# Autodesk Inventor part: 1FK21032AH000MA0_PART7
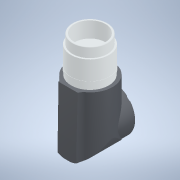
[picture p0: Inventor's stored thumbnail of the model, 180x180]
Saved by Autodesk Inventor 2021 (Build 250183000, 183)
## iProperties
Created: 2025-04
Part Number: 1FK21032AH000MA0_PART7
Material: Generic
Catalog Web Link: www.3dfindit.com
Description: -Servo synchronous motor
Document SubType Name: Modeling
Designer: psAdmin
Mass: 11.1504 g
Surface Area: 35.8996 cm^2
Volume: 11.1504 cm^3
Density: 1 g/cm^3
Appearance: PSOLRGB-176-176-176
Category: PARTsolutions
Title: 1FK21032AH000MA0_PART7
Author: Cadenas PARTsolutions
Comments: Servo synchronous motor
Sending System: PARTsolutions
Preprocessor: ST-DEVELOPER v19.3
PSOL_IDENT_0: {$CADENAS_DATA/23d-libs/siemens_ag/_cat_/45/10/1fk21032ah000ma0.prj},213 {VTYP=3D},{NB=1FK21032AH000
PSOL_IDENT_1: MA0_PART7},{LINA=1FK21032AH000MA0_PART7},{NN=1FK21032AH000MA0_PART7},{NOPRJ=TRUE},{DATE=19.08.2025 1
PSOL_IDENT_2: 4:00:35},{GEOMDATE=30.07.2025 02:02:03},{VERSION=},{LINEID=10},{WBVAR=},{WBNUMERIC=}  {NB=1FK21032AH
PSOL_IDENT_3: 000MA0_PART7},{LINA=1FK21032AH000MA0_PART7},{KT=DUMMY},{PREVIEW=../../../_pool_/14/8e/p_d211_xx_0042
PSOL_IDENT_4: 6j.png},{DESCSHORT=SIMOTICS S-1FK2 HD, SINAMICS S210 3AC 400V-480V, 0.59 Nm, 4500 rpm},{DESCLONG=SIM
PSOL_IDENT_5: OTICS S-1FK2 HD servo motor M0=0.64 Nm; PN = 0.28 kW at nN=4500 rpm (380-480 V); PN = 0.167 kW at nN=
PSOL_IDENT_6: 2500 rpm (200-240 V); degree of protection IP64; cylindrical shaft D14 x 30 mm; absolute encoder 22-
PSOL_IDENT_7: bit + 12-bit multiturn (encoder AM22DQC); with OCC interface; plug size M17, rotatable; SIMOTICS S-1
PSOL_IDENT_8: FK2 servomotorfor a wide range of uses in industrial environments. SIMOTICS S‑1FK2 servomotors are c
PSOL_IDENT_9: ompact synchronous motors with a high dynamic performance that set themselves apart as a result of t
PSOL_IDENT_10: heir high power density, degree of protection and overload capability. The motors are available in t
PSOL_IDENT_11: wo variants: as High Dynamic variant (highest dynamic performance as a result of the low intrinsic m
PSOL_IDENT_12: oment of inertia for applications demanding a high dynamic performance with low moved masses) - and
PSOL_IDENT_13: as Compact variant (precise and stable closed-loop control for medium up to large moved masses as a
PSOL_IDENT_14: result of a medium intrinsic moment of inertia). SIMOTICSS‑1FK2 servomotors fully exploit their stre
PSOL_IDENT_15: ngths in a system with the SINAMICSS210 frequency converter and simple connection using the one cabl
PSOL_IDENT_16: e connection (OCC). Advantages include the short control and positioning times, fast and precise cor
PSOL_IDENT_17: rection of disturbing quantities as well as stable control with a high dynamic performance. The serv
PSOL_IDENT_18: o motors can be configured to address a wide range of requirements. For example with and without hol
PSOL_IDENT_19: ding brake, IP64 or IP65 degree of protection, singleturn or multiturn absolute encoders - to name j
PSOL_IDENT_20: ust a few. Further, the servomotors are available in different shaft heights extending from 20 to 10
PSOL_IDENT_21: 0. A shaft sealing ring is available to achieve an IP65 degree of protection and for subsequent moun
PSOL_IDENT_22: ting at the motor or as spare part. SIMOTICS - the optimum motor for each and every motion control a
PSOL_IDENT_23: pplication.},{INTNO=195125335004},{SUPPLIERALTNO=1FK2103-2AH00-0MA0},{MANUID=1FK21032AH000MA0},{MANU
PSOL_IDENT_24: NAME=Siemens},{MANUTYPEDESC=SYNCHRONOUS MOTOR 1FK2 HD 0,64 NM},{AAU732=SIMOTICS},{AAO057=S-1FK2},{AA
PSOL_IDENT_25: U734=SIMOTICS S-1FK2 HD servo motor M0=0.64 Nm; PN = 0.28 kW at nN=4500 rpm (380-480 V); PN = 0.167
PSOL_IDENT_26: kW at nN=2500 rpm (200-240 V); degree of protection IP64; cylindrical shaft D14 x 30 mm; absolute en
PSOL_IDENT_27: coder 22-bit + 12-bit multiturn (encoder AM22DQC); with OCC interface; plug size M17, rotatable;},{A
PSOL_IDENT_28: AW338=SYNCHRONOUS MOTOR 1FK2 HD 0,64 NM},{AAO742=SIMOTICS},{AAO663=4034106444624},{NOCUPEROU=1},{PRI
PSOL_IDENT_29: CEQUANTITY=1},{QUANTITYMIN=1},{QUANTITYINT=1},{CTN=85015100},{COO=RO},{AAO676=1FK2103-2AH00-0MA0},{A
PSOL_IDENT_30: AO677=Siemens AG},{ORDERUNIT=C62},{CONTENTUNIT=C62}
NB: 1FK21032AH000MA0_PART7
NT: Servo synchronous motor
NBSYN: $MANUID._PART7
LINA: 1FK21032AH000MA0_PART7
CATALOG: SIEMENS
PREVIEW: ../../../_pool_/14/8e/p_d211_xx_00426j.png
DESCSHORT: SIMOTICS S-1FK2 HD, SINAMICS S210 3AC 400V-480V, 0.59 Nm, 4500 rpm
DESCLONG: SIMOTICS S-1FK2 HD servo motor M0=0.64 Nm; PN = 0.28 kW at nN=4500 rpm (380-480 V); PN = 0.167 kW at nN=2500 rpm (200-240 V); degree of protection IP64; cylindr
INTNO: 195125335004
SUPPLIERALTNO: 1FK2103-2AH00-0MA0
MANUID: 1FK21032AH000MA0
MANUNAME: Siemens
MANUTYPEDESC: SYNCHRONOUS MOTOR 1FK2 HD 0,64 NM
AAU732: SIMOTICS
AAO057: S-1FK2
AAU734: SIMOTICS S-1FK2 HD servo motor M0=0.64 Nm; PN = 0.28 kW at nN=4500 rpm (380-480 V); PN = 0.167 kW at nN=2500 rpm (200-240 V); degree of protection IP64; cylindr
AAW338: SYNCHRONOUS MOTOR 1FK2 HD 0,64 NM
AAO742: SIMOTICS
AAO663: 4034106444624.0
NOCUPEROU: 1
PRICEQUANTITY: 1
QUANTITYMIN: 1
QUANTITYINT: 1
CTN: 85015100
COO: RO
ARTICLENO: 1FK21032AH000MA0_PART7
BOMINFO: 1FK21032AH000MA0_PART7
CREATOR: CADENAS GmbH
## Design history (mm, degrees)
feature "2025_04_17_15_00_20_0728"
body "Solid1"
